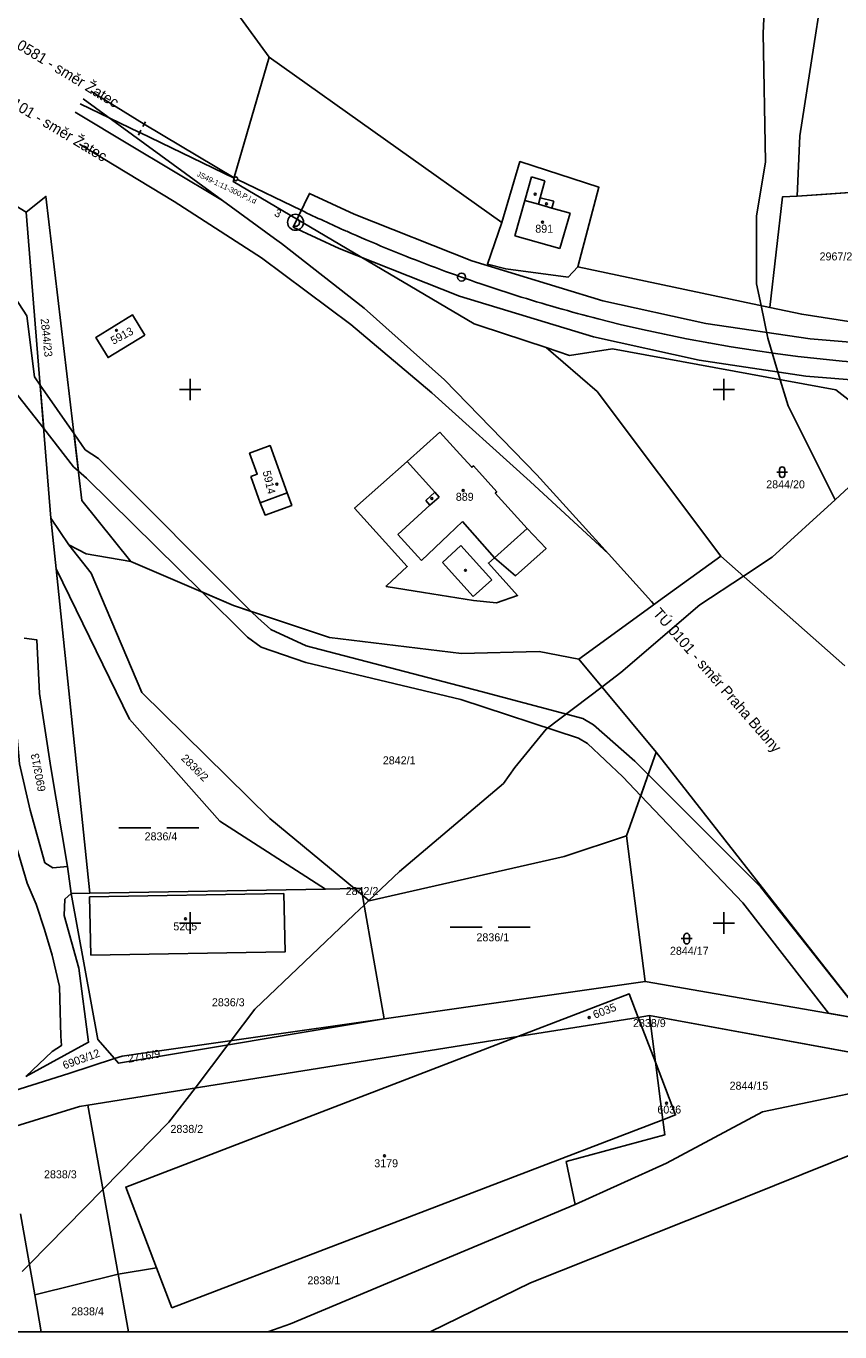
# Model space of a CAD drawing. Extents: x -800194 to -799297, y -1007177 to -1006761.
# Drawn here: x -799830.8 to -799678.2, y -1007176.6 to -1006931.9 of the extents above; entities that cross this region are included whole.
import ezdxf

# ---------------------------------------------------------------- set-up
doc = ezdxf.new("R2010")
doc.units = 0
for name, color, linetype in [('02_Osa_koleje', 7, 'Continuous'), ('_návrh', 7, 'Continuous'), ('_popvyt', 7, 'Continuous'), ('_Vrstva 7 - Přesunutá', 7, 'Continuous'), ('BPEJ', 7, 'Continuous'), ('Dočasné zábory', 7, 'Continuous'), ('Legenda 1', 7, 'Continuous'), ('Pozemky SŽDC', 7, 'Continuous'), ('Pozemky ČD', 7, 'Continuous'), ('Ramove udaje', 7, 'Continuous'), ('Vrstva 53', 7, 'Continuous'), ('Vrstva 55', 7, 'Continuous'), ('Vrstva 56', 7, 'Continuous'), ('Vrstva 57', 7, 'Continuous'), ('Vrstva 58', 7, 'Continuous'), ('Vrstva 59', 7, 'Continuous')]:
    doc.layers.add(name, color=color, linetype=linetype)

msp = doc.modelspace()

# ---------------------------------------------------------------- linework, layer by layer
at = {"layer": '02_Osa_koleje'}
msp.add_lwpolyline([(-799770.68, -1006970.33), (-799769.77, -1006970.73), (-799768.85, -1006971.13), (-799767.93, -1006971.53), (-799767.02, -1006971.93), (-799766.1, -1006972.32), (-799765.17, -1006972.71), (-799764.25, -1006973.09), (-799763.33, -1006973.48), (-799762.4, -1006973.86), (-799761.48, -1006974.24), (-799760.55, -1006974.61), (-799759.62, -1006974.98), (-799758.69, -1006975.35), (-799757.76, -1006975.71), (-799756.83, -1006976.08), (-799755.89, -1006976.43), (-799754.96, -1006976.79), (-799754.02, -1006977.14), (-799753.09, -1006977.49), (-799752.15, -1006977.84), (-799751.21, -1006978.18), (-799750.27, -1006978.52), (-799749.33, -1006978.86), (-799748.39, -1006979.19), (-799747.44, -1006979.52), (-799746.5, -1006979.85), (-799745.55, -1006980.17), (-799744.6, -1006980.5), (-799743.66, -1006980.81), (-799742.71, -1006981.13), (-799741.76, -1006981.44), (-799740.81, -1006981.75), (-799739.85, -1006982.05), (-799738.9, -1006982.36), (-799737.95, -1006982.66), (-799736.99, -1006982.95), (-799736.03, -1006983.24), (-799735.08, -1006983.53), (-799734.12, -1006983.82), (-799733.16, -1006984.1), (-799732.2, -1006984.38), (-799731.24, -1006984.66), (-799730.28, -1006984.93), (-799729.31, -1006985.2), (-799728.35, -1006985.47), (-799727.38, -1006985.73), (-799726.42, -1006985.99), (-799725.45, -1006986.25), (-799724.49, -1006986.5), (-799723.52, -1006986.75)], dxfattribs=at)
for centre, radius, start, end in [((-799651.02, -1006703.89), 292, 255.6249, 308.2052), ((-799645.75, -1006688.81), 308, 244.3251, 246.0688)]:
    msp.add_arc(centre, radius, start, end, dxfattribs=at)
at = {"layer": '_návrh'}
for p, q in [((-799820.1, -1006945.48), (-799793.94, -1006964.58)), ((-799818.64, -1006944.05), (-799808.62, -1006950.25)), ((-799820.64, -1006946.46), (-799809.51, -1006951.84)), ((-799808.88, -1006950.67), (-799808.37, -1006949.81)), ((-799791.76, -1006960.32), (-799808.62, -1006950.24)), ((-799809.7, -1006952.29), (-799809.26, -1006951.38)), ((-799791.77, -1006960.35), (-799809.48, -1006951.84)), ((-799791.14, -1006960.65), (-799779.19, -1006966.4))]:
    msp.add_line(p, q, dxfattribs=at)
for points in [[(-799821.59, -1006948.01), (-799811.06, -1006954.32), (-799803.75, -1006958.71), (-799793.94, -1006964.58), (-799784.22, -1006971.67), (-799782.91, -1006972.63), (-799767.42, -1006984.72), (-799752.33, -1006998.17), (-799735.03, -1007016), (-799721.62, -1007030.81), (-799713.56, -1007039.73), (-799713.11, -1007040.22)], [(-799820.76, -1006954), (-799803, -1006964.74), (-799786.68, -1006975.32), (-799769.88, -1006987.81), (-799754.74, -1007000.64), (-799736.31, -1007017.26), (-799721.62, -1007030.81)]]:
    msp.add_lwpolyline(points, dxfattribs=at)
for centre, radius in [((-799791.46, -1006960.5), 0.35), ((-799780.27, -1006968.65), 1.5)]:
    msp.add_circle(centre, radius, dxfattribs=at)
for start, end in [(334.3251, 64.3251), (244.3251, 334.3251)]:
    msp.add_arc((-799780.27, -1006968.65), 0.75, start, end, dxfattribs=at)
at = {"layer": '_Vrstva 7 - Přesunutá'}
msp.add_circle((-799749.15, -1006978.93), 0.75, dxfattribs=at)
at = {"layer": 'BPEJ'}
for points in [[(-799679.12, -1007020.67), (-799687.92, -1007003.07), (-799689.39, -1006998.15), (-799691.73, -1006990.36), (-799693, -1006984.25), (-799693.85, -1006980.19), (-799693.85, -1006967.48), (-799692.15, -1006957.31), (-799692.58, -1006933.17), (-799691.73, -1006914.1)], [(-799433.31, -1006923), (-799445.59, -1006934.44), (-799448.98, -1006934.86), (-799460.49, -1006939.26), (-799472.28, -1006943.76), (-799482.03, -1006946.72), (-799486.69, -1006947.15), (-799491.35, -1006948.42), (-799502.85, -1006945.54), (-799507.36, -1006944.41), (-799515.07, -1006942.49), (-799532.02, -1006943.33), (-799567.6, -1006955.2), (-799570.57, -1006956.47), (-799576.08, -1006956.47), (-799584.12, -1006958.16), (-799598.95, -1006964.52), (-799621.99, -1006980.43), (-799662.84, -1007008.64), (-799667.29, -1007011.71), (-799675.63, -1007017.47), (-799679.12, -1007020.67)], [(-799679.12, -1007020.67), (-799690.88, -1007031.45), (-799696.28, -1007034.99), (-799704.44, -1007040.35), (-799719.27, -1007053.06), (-799722.81, -1007055.75), (-799733.25, -1007063.65), (-799739.18, -1007070.85), (-799741.3, -1007073.82), (-799760.79, -1007090.34), (-799766.53, -1007095.79), (-799767.4, -1007096.63), (-799769.26, -1007098.39), (-799787.9, -1007116.18), (-799792.35, -1007122.04), (-799792.97, -1007122.86), (-799799.12, -1007130.95), (-799804, -1007137.36), (-799816.36, -1007149.92), (-799830.18, -1007163.95), (-799831.53, -1007165.33)], [(-799755.05, -1007176.65), (-799736.21, -1007167.44), (-799701.05, -1007153.46), (-799674.78, -1007142.87), (-799652.76, -1007135.67), (-799639.4, -1007132.13), (-799638.35, -1007131.86), (-799625.22, -1007128.89), (-799623.77, -1007128.77), (-799610.39, -1007127.62), (-799604.46, -1007126.35), (-799589.63, -1007124.66), (-799581.58, -1007123.81), (-799570.99, -1007120), (-799524.81, -1007111.52), (-799509.14, -1007107.29), (-799494.74, -1007104.74), (-799480.75, -1007102.63), (-799465.08, -1007100.08), (-799454.28, -1007099.52)]]:
    msp.add_lwpolyline(points, dxfattribs=at)
at = {"layer": 'Dočasné zábory'}
msp.add_lwpolyline([(-799834.59, -1006980.15), (-799830.67, -1006986.18), (-799829.24, -1006997.61), (-799828.14, -1006999.18), (-799827.49, -1007007.33), (-799833.05, -1007000.26)], dxfattribs=at)
at = {"layer": 'Legenda 1'}
msp.add_lwpolyline([(-800193.4, -1007176.65), (-799312.4, -1007176.65), (-799312.4, -1006766.65), (-800193.4, -1006766.65)], close=True, dxfattribs=at)
at = {"layer": 'Pozemky SŽDC'}
msp.add_lwpolyline([(-799664.43, -1006999.09), (-799684.6, -1006997.48), (-799704.62, -1006994.49), (-799724.39, -1006990.14), (-799749.55, -1006982.49), (-799772.1, -1006973.53), (-799780.71, -1006969.55), (-799777.67, -1006963.24), (-799769.26, -1006967.13), (-799747.23, -1006975.89), (-799722.65, -1006983.36), (-799703.35, -1006987.61), (-799683.81, -1006990.52), (-799664.23, -1006992.09)], dxfattribs=at)
for points in [[(-799797.84, -1007037.95), (-799791.91, -1007040.49), (-799788.57, -1007041.6), (-799817.24, -1007012.92), (-799819.73, -1007011.29), (-799821.79, -1007008.32), (-799820.96, -1007015.29), (-799819.49, -1007016.62)], [(-799673.33, -1007118.14), (-799693.11, -1007093.25), (-799714.14, -1007072.19), (-799715.54, -1007076.14), (-799696.4, -1007096.25), (-799680.35, -1007116.92)]]:
    msp.add_lwpolyline(points, close=True, dxfattribs=at)
at = {"layer": 'Pozemky ČD'}
for points in [[(-799828.14, -1006999.18), (-799821.79, -1007008.32), (-799820.96, -1007015.29), (-799821.87, -1007014.48), (-799827.49, -1007007.33)], [(-799788.57, -1007041.6), (-799787.36, -1007042.81), (-799784.88, -1007044.99), (-799778.25, -1007048.05), (-799745.44, -1007056.58), (-799726.42, -1007061.68), (-799724.38, -1007062.83), (-799716.64, -1007069.69), (-799714.14, -1007072.19), (-799715.54, -1007076.14), (-799718.92, -1007072.58), (-799725.51, -1007066.38), (-799727.21, -1007065.37), (-799749.27, -1007058.08), (-799778.37, -1007051.16), (-799786.69, -1007048.31), (-799789.28, -1007046.39), (-799797.84, -1007037.95), (-799797.84, -1007037.95), (-799791.91, -1007040.49)]]:
    msp.add_lwpolyline(points, close=True, dxfattribs=at)
at = {"layer": 'Ramove udaje'}
for p, q in [((-799800, -1006998), (-799800, -1007002)), ((-799700, -1006998), (-799700, -1007002)), ((-799802, -1007000), (-799800, -1007000)), ((-799800, -1007000), (-799798, -1007000)), ((-799702, -1007000), (-799700, -1007000)), ((-799700, -1007000), (-799698, -1007000)), ((-799802, -1007100), (-799800, -1007100)), ((-799800, -1007098), (-799800, -1007102)), ((-799800, -1007100), (-799798, -1007100)), ((-799702, -1007100), (-799700, -1007100)), ((-799700, -1007098), (-799700, -1007102)), ((-799700, -1007100), (-799698, -1007100))]:
    msp.add_line(p, q, dxfattribs=at)
at = {"layer": 'Vrstva 53'}
for points in [[(-799831.75, -1006884.86), (-799830.3, -1006886.5), (-799824.73, -1006892.78), (-799821.02, -1006893.98), (-799817.05, -1006894.06), (-799808.6, -1006894.22), (-799715.17, -1006892.15), (-799698.08, -1006856.38), (-799691.64, -1006842.91), (-799685.69, -1006830.46), (-799684.1, -1006830.47), (-799704.46, -1006903.31), (-799691.31, -1006907.33), (-799679.26, -1006911.01), (-799685.71, -1006952.41), (-799686.25, -1006963.73), (-799670.17, -1006962.64), (-799668.03, -1006961.74), (-799668, -1006962.02), (-799667.43, -1006981.06), (-799637.16, -1006982.06), (-799603.07, -1006978.39), (-799559.64, -1006968.48), (-799519.68, -1006952.01)], [(-799673.33, -1007118.14), (-799714.71, -1007110.97), (-799718.21, -1007083.69), (-799729.93, -1007087.54), (-799766.47, -1007095.84), (-799767.73, -1007094.8), (-799769.22, -1007093.56), (-799785.06, -1007080.42), (-799809.11, -1007056.81), (-799818.59, -1007034.4), (-799822.79, -1007029.13), (-799826.14, -1007024.13), (-799830.75, -1006966.73), (-799839.73, -1006961.33)], [(-799662.13, -1007129.03), (-799692.74, -1007135.4), (-799710.71, -1007144.99), (-799727.84, -1007152.76), (-799729.51, -1007144.72), (-799711.04, -1007139.72), (-799711.41, -1007136.88), (-799712.8, -1007126.1), (-799713.93, -1007117.37), (-799664.74, -1007126.35)]]:
    msp.add_lwpolyline(points, dxfattribs=at)
at = {"layer": 'Vrstva 55'}
for p, q in [((-799785.23, -1006937.71), (-799741.57, -1006968.68)), ((-799830.75, -1006966.73), (-799839.73, -1006961.33)), ((-799826.14, -1007024.13), (-799830.75, -1006966.73)), ((-799727.37, -1006976.97), (-799691.32, -1006984.61)), ((-799825.16, -1007033.58), (-799826.14, -1007024.13)), ((-799822.79, -1007029.13), (-799826.14, -1007024.13)), ((-799700.54, -1007031.23), (-799677.3, -1007051.77)), ((-799818.85, -1007094.38), (-799825.16, -1007033.58)), ((-799727.16, -1007050.52), (-799712.65, -1007067.97)), ((-799718.21, -1007083.69), (-799712.65, -1007067.97)), ((-799712.65, -1007067.97), (-799673.33, -1007118.14)), ((-799714.71, -1007110.97), (-799718.21, -1007083.69)), ((-799823.03, -1007089.38), (-799822.31, -1007094.44)), ((-799822.31, -1007094.44), (-799818.85, -1007094.38)), ((-799774.66, -1007093.65), (-799818.85, -1007094.38)), ((-799774.66, -1007093.65), (-799769.22, -1007093.56)), ((-799767.73, -1007094.8), (-799769.22, -1007093.56)), ((-799714.71, -1007110.97), (-799763.63, -1007117.94)), ((-799673.33, -1007118.14), (-799714.71, -1007110.97)), ((-799716.02, -1007117.7), (-799738.61, -1007121.3)), ((-799716.02, -1007117.7), (-799713.93, -1007117.37)), ((-799712.8, -1007126.1), (-799716.02, -1007117.7)), ((-799713.93, -1007117.37), (-799664.74, -1007126.35)), ((-799713.93, -1007117.37), (-799712.8, -1007126.1)), ((-799819.2, -1007134.15), (-799738.61, -1007121.3)), ((-799711.41, -1007136.88), (-799712.8, -1007126.1)), ((-799819.2, -1007134.15), (-799813.5, -1007165.83)), ((-799803.46, -1007172.11), (-799711.41, -1007136.88)), ((-799727.84, -1007152.76), (-799781.23, -1007175.14)), ((-799831.81, -1007154.54), (-799829.18, -1007169.73)), ((-799829.18, -1007169.73), (-799813.5, -1007165.83)), ((-799806.31, -1007164.66), (-799813.5, -1007165.83)), ((-799813.5, -1007165.83), (-799811.57, -1007176.65)), ((-799806.31, -1007164.66), (-799803.46, -1007172.11)), ((-799829.18, -1007169.73), (-799827.98, -1007176.65)), ((-799781.23, -1007175.14), (-799785.48, -1007176.65))]:
    msp.add_line(p, q, dxfattribs=at)
for points in [[(-799815.49, -1006895.78), (-799807.53, -1006905.17), (-799803.4, -1006912.69), (-799785.23, -1006937.71)], [(-799686.25, -1006963.73), (-799685.71, -1006952.41), (-799679.26, -1006911.01)], [(-799785.23, -1006937.71), (-799791.69, -1006959.99), (-799791.97, -1006960.97), (-799746.76, -1006987.67), (-799745.68, -1006988.03), (-799733.28, -1006992.13)], [(-799741.57, -1006968.68), (-799738.19, -1006957.26), (-799723.4, -1006962.09), (-799727.37, -1006976.97)], [(-799686.25, -1006963.73), (-799681.51, -1006963.46), (-799670.17, -1006962.64), (-799668.03, -1006961.74)], [(-799811.13, -1007032.26), (-799820.31, -1007020.81), (-799827.08, -1006963.79), (-799830.75, -1006966.73)], [(-799691.32, -1006984.61), (-799688.98, -1006963.88), (-799686.25, -1006963.73)], [(-799741.57, -1006968.68), (-799744.25, -1006976.52), (-799740.85, -1006977.38), (-799729.15, -1006978.91), (-799727.37, -1006976.97)], [(-799691.32, -1006984.61), (-799685.35, -1006985.87), (-799674.55, -1006987.57), (-799667.43, -1006981.06)], [(-799808.51, -1006989.81), (-799810.83, -1006986), (-799817.7, -1006990.24), (-799815.41, -1006994.01), (-799808.51, -1006989.81)], [(-799667.22, -1007009.16), (-799678.94, -1007000.07), (-799720.83, -1006992.39), (-799728.88, -1006993.59), (-799733.28, -1006992.13)], [(-799733.28, -1006992.13), (-799723.72, -1007000.38), (-799700.54, -1007031.23)], [(-799753.19, -1007008), (-799759.37, -1007013.49), (-799769.21, -1007022.23), (-799759.34, -1007033.19), (-799763.24, -1007036.79), (-799763.26, -1007036.9), (-799756.25, -1007038.04), (-799746.93, -1007039.54), (-799742.61, -1007039.98), (-799738.64, -1007038.58), (-799744.1, -1007032.52), (-799742.99, -1007031.53), (-799739, -1007034.9), (-799733.28, -1007029.82), (-799736.83, -1007026.06), (-799742.84, -1007019.43), (-799742.54, -1007019.16), (-799746.93, -1007014.32), (-799747.23, -1007014.58), (-799749.47, -1007012.1), (-799753.19, -1007008)], [(-799788.68, -1007016.29), (-799786.88, -1007021.22), (-799785.99, -1007023.53), (-799780.99, -1007021.72), (-799781.84, -1007019.38), (-799785.05, -1007010.5), (-799788.88, -1007011.9), (-799787.45, -1007015.84), (-799788.68, -1007016.29)], [(-799769.22, -1007093.56), (-799785.06, -1007080.42), (-799809.11, -1007056.81), (-799818.59, -1007034.4), (-799822.79, -1007029.13)], [(-799811.13, -1007032.26), (-799819.54, -1007030.79), (-799822.79, -1007029.13)], [(-799700.54, -1007031.23), (-799712.19, -1007039.67), (-799713.65, -1007040.73), (-799727.16, -1007050.52)], [(-799825.16, -1007033.58), (-799811.39, -1007061.77), (-799794.49, -1007080.93), (-799774.66, -1007093.65)], [(-799727.16, -1007050.52), (-799734.57, -1007049.13), (-799749.18, -1007049.49), (-799773.9, -1007046.46), (-799791.91, -1007040.49), (-799811.13, -1007032.26)], [(-799823.03, -1007089.38), (-799825.77, -1007089.63), (-799827.26, -1007088.72), (-799830.02, -1007078.85), (-799832.03, -1007070.18), (-799833.02, -1007058.82), (-799832.71, -1007046.42)], [(-799831.14, -1007046.62), (-799828.75, -1007046.93), (-799828.27, -1007056.97), (-799826.13, -1007070.87), (-799825.16, -1007076.77), (-799823.03, -1007089.38)], [(-799858.84, -1007065.67), (-799858.76, -1007060.77), (-799858.72, -1007059.86), (-799857.59, -1007058.97), (-799845.38, -1007056.13), (-799841.77, -1007056.79), (-799839.5, -1007058.21), (-799837.43, -1007060.68), (-799836.99, -1007067.77), (-799836.14, -1007072.71), (-799834.61, -1007079.6), (-799832.83, -1007084.94), (-799830.58, -1007092.52), (-799828.9, -1007096.44), (-799827.32, -1007101.2), (-799825.89, -1007106.02), (-799824.52, -1007111.92), (-799824.25, -1007121.19), (-799824.17, -1007122.98), (-799825.87, -1007124.09), (-799830.82, -1007128.75)], [(-799718.21, -1007083.69), (-799729.93, -1007087.54), (-799766.47, -1007095.84), (-799767.73, -1007094.8)], [(-799830.82, -1007128.75), (-799819.06, -1007122.35), (-799820.88, -1007108.46), (-799823.65, -1007098.62), (-799823.55, -1007095.54), (-799822.31, -1007094.44)], [(-799822.31, -1007094.44), (-799817.36, -1007121.82), (-799814.24, -1007125.43)], [(-799782.48, -1007094.48), (-799818.89, -1007095.11), (-799818.65, -1007106.02), (-799782.2, -1007105.4), (-799782.48, -1007094.48)], [(-799769.22, -1007093.56), (-799767.95, -1007093.54), (-799767.73, -1007094.8)], [(-799767.73, -1007094.8), (-799767.52, -1007095.98), (-799763.63, -1007117.94)], [(-799738.61, -1007121.3), (-799717.71, -1007113.29), (-799716.02, -1007117.7)], [(-799763.63, -1007117.94), (-799813.49, -1007126.3), (-799814.24, -1007125.43)], [(-799763.63, -1007117.94), (-799812.76, -1007124.95), (-799814.24, -1007125.43)], [(-799738.61, -1007121.3), (-799812.11, -1007149.49), (-799806.31, -1007164.66)], [(-799814.24, -1007125.43), (-799822.76, -1007128.21), (-799844.82, -1007135.16), (-799895.02, -1007147.45)], [(-799712.8, -1007126.1), (-799709.02, -1007135.97), (-799711.41, -1007136.88)], [(-799662.13, -1007129.03), (-799692.74, -1007135.4), (-799710.71, -1007144.99), (-799727.84, -1007152.76)], [(-799842.89, -1007141.21), (-799820.76, -1007134.4), (-799819.2, -1007134.15)], [(-799727.84, -1007152.76), (-799729.51, -1007144.72), (-799711.04, -1007139.72), (-799711.41, -1007136.88)]]:
    msp.add_lwpolyline(points, dxfattribs=at)
at = {"layer": 'Vrstva 56'}
for p, q in [((-799736.02, -1006960.1), (-799737.26, -1006964.54)), ((-799733.56, -1006960.86), (-799736.02, -1006960.1)), ((-799734.4, -1006964.04), (-799733.56, -1006960.86)), ((-799737.26, -1006964.54), (-799739.13, -1006971.21)), ((-799737.26, -1006964.54), (-799734.72, -1006965.27)), ((-799734.72, -1006965.27), (-799734.4, -1006964.04)), ((-799734.72, -1006965.27), (-799732.21, -1006965.99)), ((-799731.87, -1006964.71), (-799734.4, -1006964.04)), ((-799732.21, -1006965.99), (-799731.87, -1006964.71)), ((-799728.75, -1006966.91), (-799732.21, -1006965.99)), ((-799730.7, -1006973.58), (-799728.75, -1006966.91)), ((-799739.13, -1006971.21), (-799730.7, -1006973.58)), ((-799754.17, -1007019.25), (-799759.37, -1007013.49)), ((-799786.88, -1007021.22), (-799781.84, -1007019.38)), ((-799755.87, -1007020.79), (-799754.17, -1007019.25)), ((-799754.17, -1007019.25), (-799753.35, -1007020.15)), ((-799761.09, -1007027.15), (-799755.06, -1007021.69)), ((-799755.06, -1007021.69), (-799755.87, -1007020.79)), ((-799753.35, -1007020.15), (-799755.06, -1007021.69)), ((-799751.58, -1007027.23), (-799748.98, -1007024.74)), ((-799748.98, -1007024.74), (-799742.99, -1007031.53)), ((-799742.99, -1007031.53), (-799736.83, -1007026.06)), ((-799757.32, -1007031.32), (-799761.09, -1007027.15)), ((-799756.64, -1007032.07), (-799751.58, -1007027.23)), ((-799756.64, -1007032.07), (-799757.32, -1007031.32)), ((-799752.74, -1007032.43), (-799749.3, -1007029.24)), ((-799749.3, -1007029.24), (-799743.44, -1007035.69)), ((-799746.94, -1007038.81), (-799752.74, -1007032.43)), ((-799746.94, -1007038.81), (-799743.44, -1007035.69))]:
    msp.add_line(p, q, dxfattribs=at)
at = {"layer": 'Vrstva 58'}
for p, q in [((-799690.04, -1007015.49), (-799688.04, -1007015.49)), ((-799689.54, -1007014.99), (-799689.54, -1007015.99)), ((-799688.54, -1007015.99), (-799688.54, -1007014.99)), ((-799813.4, -1007082.19), (-799807.4, -1007082.19)), ((-799804.4, -1007082.19), (-799798.4, -1007082.19)), ((-799751.26, -1007100.77), (-799745.26, -1007100.77)), ((-799742.26, -1007100.77), (-799736.26, -1007100.77)), ((-799707.44, -1007102.43), (-799707.44, -1007103.43)), ((-799706.43, -1007103.43), (-799706.43, -1007102.43)), ((-799707.94, -1007102.93), (-799705.93, -1007102.93))]:
    msp.add_line(p, q, dxfattribs=at)
for centre, start, end in [((-799689.04, -1007014.99), 0, 180), ((-799689.04, -1007015.99), 180, 359.9879), ((-799706.93, -1007102.43), 0, 180), ((-799706.93, -1007103.43), 180, 359.9879)]:
    msp.add_arc(centre, 0.5, start, end, dxfattribs=at)
at = {"layer": 'Vrstva 59'}
for centre in [(-799735.33, -1006963.38), (-799733.22, -1006965.18), (-799733.96, -1006968.62), (-799813.84, -1006988.9), (-799783.77, -1007017.72), (-799748.84, -1007018.92), (-799754.7, -1007020.42), (-799748.42, -1007033.89), (-799800.9, -1007099.21), (-799725.21, -1007117.73), (-799710.71, -1007133.78), (-799763.59, -1007143.63)]:
    msp.add_circle(centre, 0.175, dxfattribs=at)

# ---------------------------------------------------------------- texts
at = {"layer": '02_Osa_koleje'}
for s, rotation, p in [('TÚ 0581 - směr Žatec', 328.6802, (-799836.39, -1006933.75)), ('TÚ 0101 - směr Žatec', 328.939, (-799838.66, -1006943.96)), ('TÚ 0101 - směr Praha Bubny', 311.117, (-799713.38, -1007042.03))]:
    msp.add_text(s, height=2, rotation=rotation, dxfattribs=at).set_placement(p)
at = {"layer": '_popvyt'}
for s, height, p in [('      JS49-1:11-300,P,l,d', 1, (-799800.97, -1006958.93)), ('3', 1.5, (-799784.39, -1006967.38))]:
    msp.add_text(s, height=height, rotation=334.3251, dxfattribs=at).set_placement(p)
at = {"layer": 'Vrstva 57'}
for s, p in [('891', (-799735.32, -1006970.6)), ('2967/2', (-799682.02, -1006975.79)), ('2844/20', (-799692.02, -1007018.52)), ('889', (-799750.22, -1007020.85)), ('2842/1', (-799763.91, -1007070.26)), ('2836/4', (-799808.57, -1007084.51)), ('2842/2', (-799770.87, -1007094.76)), ('5205', (-799803.18, -1007101.38)), ('2836/1', (-799746.35, -1007103.43)), ('2844/17', (-799710.07, -1007105.96)), ('2836/3', (-799795.95, -1007115.61)), ('2838/9', (-799717, -1007119.51)), ('2844/15', (-799698.89, -1007131.25)), ('6036', (-799712.43, -1007135.72)), ('2838/2', (-799803.72, -1007139.35)), ('3179', (-799765.51, -1007145.79)), ('2838/3', (-799827.43, -1007147.86)), ('2838/1', (-799778.04, -1007167.74)), ('2838/4', (-799822.34, -1007173.55))]:
    msp.add_text(s, height=1.5, dxfattribs=at).set_placement(p)
for s, rotation, p in [('2844/23', 276, (-799828.07, -1006986.74)), ('5913', 28, (-799814.44, -1006991.62)), ('5914', 283, (-799786.44, -1007015.38)), ('6903/13', 101, (-799827.08, -1007075.21)), ('2836/2', 315, (-799801.84, -1007069.26)), ('6035', 21, (-799724.15, -1007117.96)), ('6903/12', 20, (-799823.6, -1007127.45)), ('2716/9', 9.6773, (-799811.58, -1007126.21))]:
    msp.add_text(s, height=1.5, rotation=rotation, dxfattribs=at).set_placement(p)

doc.saveas('drawing.dxf')
